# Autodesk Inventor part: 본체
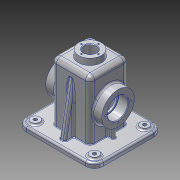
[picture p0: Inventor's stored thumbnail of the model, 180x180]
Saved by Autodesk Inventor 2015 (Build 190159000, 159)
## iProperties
Created: 2016-02
Part Number: 본체
Material: 알루미늄 6061
Document SubType Name: Modeling
Designer: Administrator
Density: 2.7 g/cm^3
Appearance: 알루미늄 - 평지
Mass: 800.036 g
Surface Area: 908.079 cm^2
Volume: 296.31 cm^3
Author: Administrator
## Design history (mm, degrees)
sketch "스케치1"
  geometry: L1 (-65, -57.5)-(65, -57.5); L2 (65, -57.5)-(65, 57.5); L3 (65, 57.5)-(-65, 57.5); L4 (-65, 57.5)-(-65, -57.5); L5 (-65, -57.5)-(65, 57.5); L6 (65, -57.5)-(-65, 57.5); 1 further point
  constraints: 12 end point, 2 midpoint, 2 parallel, 1 horizontal, 1 perpendicular
  dimensions: "d0" = 130 distance of L3.end L2.end; "d1" = 115 distance of L2.end L1.end
extrude "돌출1" new body sketch "스케치1" distance "d2" = 8; taper "d3" = 0 deg
fillet "모깎기1" dims "d4" = 15
sketch "스케치2"
  geometry: L1 (-50, -57.5)-(50, -57.5) reference; L2 (-50, -57.5)-(50, -57.5) reference; L3 (65, -42.5)-(65, 42.5) reference; L4 (50, 57.5)-(-50, 57.5) reference; L5 (-65, 42.5)-(-65, -42.5) reference; C1 r 7.5 at (50, -42.5); C2 r 7.5 at (-50, -42.5); C3 r 7.5 at (50, 42.5); C4 r 7.5 at (-50, 42.5); A1 r 15 centre (-50, -42.5) between (-65, -42.5) and (-50, -57.5) reference; A2 r 15 centre (50, -42.5) between (50, -57.5) and (65, -42.5) reference; A3 r 15 centre (50, 42.5) between (65, 42.5) and (50, 57.5) reference; A4 r 15 centre (-50, 42.5) between (-50, 57.5) and (-65, 42.5) reference; 1 further point
  constraints: 4 centre point, 1 horizontal, 1 vertical, 6 other
  dimensions: "d5" = 15 diameter of C1; "d6" = 50 horizontal distance of point (0, 0) C1.centre; "d7" = 42.5 vertical distance of point (0, 0) C1.centre; "d10" = 100 distance of C1.centre C2.centre; "d13" = 85 distance of C1.centre C3.centre
extrude "돌출2" join sketch "스케치2" distance "d16" = 3; taper "d17" = 0 deg
sketch "스케치3"
  geometry: L1 (-60, -52.5)-(60, -52.5); L2 (60, -52.5)-(60, 52.5); L3 (60, 52.5)-(-60, 52.5); L4 (-60, 52.5)-(-60, -52.5); L5 (-60, -52.5)-(60, 52.5); L6 (60, -52.5)-(-60, 52.5); 1 further point
  constraints: 12 end point, 2 midpoint, 2 parallel, 1 horizontal, 1 perpendicular
  dimensions: "d54" = 120 distance of L3.end L2.end; "d55" = 105 distance of L2.end L1.end
extrude "돌출3" join sketch "스케치3" distance "d56" = 2; taper "d57" = 0 deg
fillet "모깎기2" dims "d58" = 10
sketch "스케치4"
  geometry: L1 (5, 47.5)-(-5, 47.5); L2 (-5, 47.5)-(-5, -47.5); L3 (-5, -47.5)-(5, -47.5); L4 (5, -47.5)-(5, 47.5); L5 (5, 47.5)-(-5, -47.5); L6 (-5, 47.5)-(5, -47.5); 1 further point
  constraints: 12 end point, 2 midpoint, 2 parallel, 1 horizontal, 1 perpendicular
  dimensions: "d59" = 10 distance of L3.end L2.end; "d60" = 95 distance of L2.end L1.end
extrude "돌출4" join sketch "스케치4" distance "d61" = 100; taper "d62" = 0 deg
feature "면 기울기1" dims angle "d63" = 10 deg
feature "면 기울기2" dims angle "d64" = 10 deg
sketch "스케치5"
  geometry: L1 (-32.5, 32.5)-(32.5, 32.5); L2 (32.5, 32.5)-(32.5, -32.5); L3 (32.5, -32.5)-(-32.5, -32.5); L4 (-32.5, -32.5)-(-32.5, 32.5); L5 (-32.5, 32.5)-(32.5, -32.5); L6 (32.5, 32.5)-(-32.5, -32.5); 1 further point
  constraints: 12 end point, 2 midpoint, 2 parallel, 1 horizontal, 1 perpendicular
  dimensions: "d65" = 65 distance of L2.end L3.end; "d66" = 65 distance of L1.end L2.end
extrude "돌출5" join sketch "스케치5" distance "d67" = 100; taper "d68" = 0 deg
sketch "스케치6"
  geometry: C1 r 10.5 at (0, 0); 1 further point
  constraints: 1 centre point, 1 coincident
  dimensions: "d69" = 21 diameter of C1
extrude "돌출6" cut sketch "스케치6" stored distance "d70" = 110; taper "d71" = 0 deg
sketch "스케치7"
  geometry: L1 (-27.5, 27.5)-(27.5, 27.5); L2 (27.5, 27.5)-(27.5, -27.5); L3 (27.5, -27.5)-(-27.5, -27.5); L4 (-27.5, -27.5)-(-27.5, 27.5); L5 (-27.5, 27.5)-(27.5, -27.5); L6 (27.5, 27.5)-(-27.5, -27.5); 1 further point
  constraints: 12 end point, 2 midpoint, 2 parallel, 1 horizontal, 1 perpendicular
  dimensions: "d72" = 55 distance of L2.end L3.end; "d73" = 55 distance of L1.end L2.end
extrude "돌출7" cut sketch "스케치7" distance "d74" = 105; taper "d75" = 0 deg
sketch "스케치8"
  geometry: C1 r 20 at (0, 0); 1 further point
  constraints: 1 centre point, 1 coincident
  dimensions: "d76" = 40 diameter of C1
extrude "돌출8" join sketch "스케치8" distance "d77" = 10; taper "d78" = 0 deg
hole "구멍5" diameter "d81" = 21; stored, may be unused: countersink angle "d85" = 90 deg, drill point angle "d87" = 118 deg; dims "d79" = 10, "d80" = 10, "d82" = 7, "d83" = 4, "d84" = 2, "d86" = 21
sketch "스케치9" dims "d88" = 29
  geometry: 6 further points
  constraints: 2 vertical alignment, 1 coincident, 7 other
  dimensions: "d91" = 360 deg dimension on point (0, 0) point (0, 14.5) (derived)
hole "구멍6" sketch "스케치9" at (0, 14.5), (-14.5, 0), (0, -14.5), (14.5, 0) diameter "d93" = 2.459; stored, may be unused: countersink angle "d97" = 90 deg, drill point angle "d99" = 118 deg; dims "d94" = 7, "d95" = 4, "d96" = 2, "d98" = 9
feature "면 기울기3" dims angle "d100" = 5 deg
sketch "스케치10"
  geometry: L1 (42.5, 3)-(-42.5, 3); L2 (-42.5, 3)-(-42.5, -3); L3 (-42.5, -3)-(42.5, -3); L4 (42.5, -3)-(42.5, 3); L5 (42.5, 3)-(-42.5, -3); L6 (-42.5, 3)-(42.5, -3); 1 further point
  constraints: 12 end point, 2 midpoint, 2 parallel, 1 horizontal, 1 perpendicular
  dimensions: "d101" = 85 distance of L3.end L2.end; "d102" = 6 distance of L2.end L1.end
extrude "돌출9" join sketch "스케치10" distance "d103" = 30; taper "d104" = 0 deg
sketch "스케치11"
  geometry: L1 (108, -10)-(108, 75) reference; C1 r 27.5 at (53, 32.5); 2 further points
  constraints: 1 centre point, 1 horizontal alignment, 1 midpoint
  dimensions: "d105" = 55 diameter of C1; "d106" = 55 distance from line of L1 C1.centre
extrude "돌출10" join sketch "스케치11" distance "d107" = 15; taper "d108" = 0 deg
hole "구멍7" diameter "d111" = 30; stored, may be unused: countersink angle "d115" = 90 deg, drill point angle "d117" = 0 deg; dims "d109" = 10, "d110" = 10, "d112" = 7, "d113" = 4, "d114" = 2, "d116" = 30
hole "구멍8" diameter "d120" = 35; stored, may be unused: countersink angle "d124" = 90 deg, drill point angle "d126" = 0 deg; dims "d118" = 10, "d119" = 10, "d121" = 7, "d122" = 4, "d123" = 2, "d125" = 17
sketch "스케치12" dims "d127" = 42
  geometry: L1 (44, -35.429)-(47, -35.429) reference; L2 (47, -35.429)-(47, 35.429) reference; L3 (47, 35.429)-(44, 35.429) reference; L4 (44, 35.429)-(44, 49.571) reference; L5 (44, 49.571)-(47, 49.571) reference; L6 (47, 49.571)-(47, 57.5) reference; L7 (47, 57.5)-(55, 57.5) reference; L8 (55, 57.5)-(55, 52.5) reference; L9 (55, -52.5)-(55, -57.5) reference; L10 (55, -57.5)-(47, -57.5) reference; L11 (47, -57.5)-(47, -49.571) reference; L12 (47, -49.571)-(44, -49.571) reference; L13 (44, -49.571)-(44, -35.429) reference; L14 (55, 52.5)-(57, 52.5) reference; L15 (57, 52.5)-(57, -52.5) reference; L16 (57, -52.5)-(55, -52.5) reference; C1 r 17.5 at (0, 0) reference; C2 r 27.5 at (0, 0) reference; 6 further points
  constraints: 2 horizontal alignment, 1 coincident, 7 other
  dimensions: "d130" = 360 deg dimension on point (0, 0) point (-21, 0) (derived)
hole "구멍9" sketch "스케치12" at (-21, 0), (0, -21), (21, 0), (0, 21) diameter "d132" = 3.242; stored, may be unused: countersink angle "d136" = 90 deg, drill point angle "d138" = 118 deg; dims "d133" = 8, "d134" = 4, "d135" = 2, "d137" = 10
chamfer "모따기1" distance "d139" = 1; stored, may be unused: second distance "d140" = 2, angle "d141" = 45 deg
fillet "모깎기3" dims "d142" = 0.3
sketch "스케치13"
  geometry: L1 (27.5, 27.5)-(-27.5, 27.5); L2 (-27.5, 27.5)-(-27.5, -27.5); L3 (-27.5, -27.5)-(27.5, -27.5); L4 (27.5, -27.5)-(27.5, 27.5); L5 (27.5, 27.5)-(-27.5, -27.5); L6 (-27.5, 27.5)-(27.5, -27.5); 1 further point
  constraints: 12 end point, 2 midpoint, 2 parallel, 1 horizontal, 1 perpendicular
extrude "돌출11" cut sketch "스케치13" distance "d143" = 50; taper "d144" = 0 deg
fillet "모깎기4" dims "d145" = 3
fillet "모깎기5" dims "d146" = 3
fillet "모깎기6" dims "d147" = 3
fillet "모깎기7" dims "d148" = 3
fillet "모깎기9" dims "d150" = 3
fillet "모깎기11" dims "d152" = 8
fillet "모깎기12" dims "d153" = 8
fillet "모깎기14" dims "d155" = 3
fillet "모깎기15" dims "d156" = 3
sketch "스케치14"
  geometry: L1 (18, 5.375)-(18, 43.625) reference; L2 (0, 57)-(-92, 57) reference; 3 further points
  constraints: 1 other
  dimensions: "d157" = 26 distance from line of point (-8, 24.5) L1; "d158" = 32.5 distance from line of point (-8, 24.5) L2
feature "엠보싱1" sketch "스케치14" dims "d159" = 0.5, "d160" = 0
chamfer "모따기2" distance "d161" = 1; stored, may be unused: second distance "d162" = 2, angle "d163" = 45 deg
hole "구멍10" diameter "d166" = 6; stored, may be unused: countersink angle "d170" = 90 deg, drill point angle "d172" = 0 deg; dims "d164" = 10, "d165" = 10, "d167" = 8, "d168" = 4, "d169" = 2, "d171" = 6
fillet "모깎기16" dims "d173" = 3
fillet "모깎기17" dims "d174" = 1
fillet "모깎기18" dims "d175" = 0.3
node "솔리드1"
mirror "대칭1"
mirror "대칭2"
mirror "대칭3"
node "투영된 루프1"
node "절단 모서리 투영1"
